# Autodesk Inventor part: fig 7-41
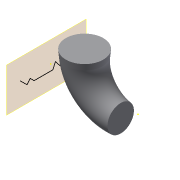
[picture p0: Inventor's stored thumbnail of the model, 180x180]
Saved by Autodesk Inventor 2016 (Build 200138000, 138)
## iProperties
Created: 2011-07
Part Number: fig 7-41
Material: Generic
Document SubType Name: Modeling
Designer: CadCim
Density: 1 g/cm^3
Appearance: Default
Author: CadCim
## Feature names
1. Sweep1
## Parameters: d0 = 5 deg, d1 = -14.75 mm, d2 = 0
